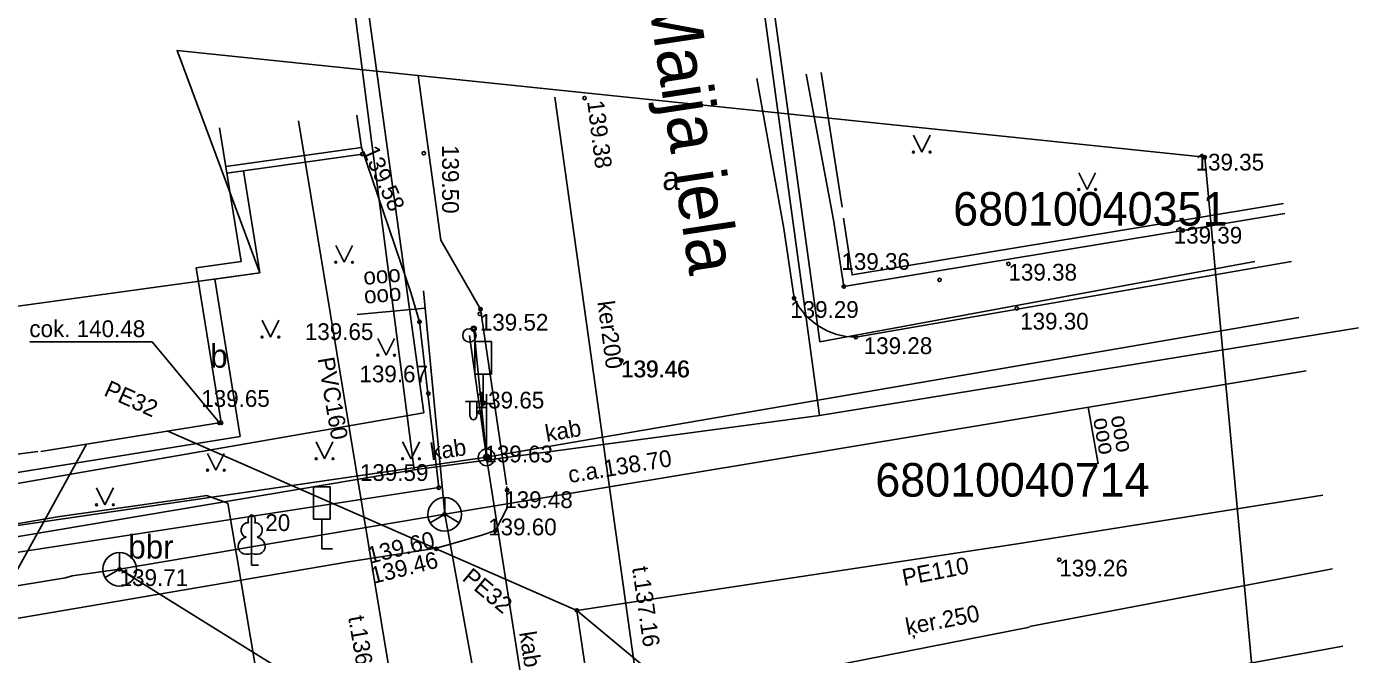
# Model space of a CAD drawing. Extents: x 728492 to 729038, y 272968 to 273171.
# Drawn here: x 728950.66 to 728990.4, y 273126.6 to 273145.31 of the extents above; entities that cross this region are included whole.
import ezdxf

# ---------------------------------------------------------------- set-up
doc = ezdxf.new("R2010")
doc.units = 0
for name, color, linetype in [('APGR_SARK_####_####_#', 7, 'Continuous'), ('APGS_ELEM_####_####_#', 7, 'Continuous'), ('BUVE_BDET_####_####_#', 7, 'Continuous'), ('BUVE_BDET_####_TKST_#', 7, 'Continuous'), ('BUVE_EKAS_####_####_#', 7, 'Continuous'), ('CELI_CAPM_####_####_#', 7, 'Continuous'), ('CELI_CMAL_####_####_#', 7, 'Continuous'), ('CELI_CSEG_####_TKST_#', 7, 'Continuous'), ('CELI_ELEM_####_####_#', 7, 'Continuous'), ('CELI_IELA_####_TKST_#', 7, 'Continuous'), ('ELEK_ELEM_####_####_#', 7, 'Continuous'), ('ELEK_SAIT_####_####_#', 7, 'Continuous'), ('ELEK_STUT_####_####_#', 7, 'Continuous'), ('ELEK_VADP_ZSPR_####_#', 7, 'Continuous'), ('ELEK_VADV_ZSPR_####_#', 7, 'Continuous'), ('ELEK_VADV_ZSPR_TKST_#', 7, 'Continuous'), ('RAMI_UZMR_####_####_#', 7, 'Continuous'), ('RELJ_AATZ_####_TKST_#', 7, 'Continuous'), ('RELJ_ELEM_####_####_#', 7, 'Continuous'), ('ROBZ_KADS_####_TKST_#', 7, 'Continuous'), ('ROBZ_UZMR_####_####_#', 7, 'Continuous'), ('SAKK_ELEM_####_####_#', 7, 'Continuous'), ('SAKK_ELEM_####_TKST_#', 7, 'Continuous'), ('SAKK_IZVK_####_TKST_#', 7, 'Continuous'), ('SAKK_KKAN_####_####_#', 7, 'Continuous'), ('SAKK_KKAN_####_TKST_#', 7, 'Continuous'), ('SKAN_VADP_PAST_####_#', 7, 'Continuous'), ('SKAN_VADP_PAST_TKST_#', 7, 'Continuous'), ('TERT_DIAM_####_TKST_#', 7, 'Continuous'), ('TERT_ELEM_####_####_#', 7, 'Continuous'), ('TERT_KRND_####_####_#', 7, 'Continuous'), ('UDTK_VADP_UDEN_####_#', 7, 'Continuous'), ('UDTK_VADP_UDEN_TKST_#', 7, 'Continuous')]:
    doc.layers.add(name, color=color, linetype=linetype)

msp = doc.modelspace()

# ---------------------------------------------------------------- linework, layer by layer
at = {"layer": 'APGR_SARK_####_####_#'}
for points in [[(728971.466, 273156.636), (728974.331, 273135.918)], [(728959.442, 273155.987), (728962.51, 273133.798)], [(728987.311, 273138.313), (728974.331, 273135.918)], [(728962.51, 273133.798), (728824.842, 273109.886)]]:
    msp.add_lwpolyline(points, dxfattribs=at)
at = {"layer": 'APGS_ELEM_####_####_#'}
for p, q in [((728964.384, 273134.141), (728963.749, 273134.136)), ((728963.884, 273134.137), (728963.884, 273133.745)), ((728964.094, 273134.139), (728964.094, 273133.745)), ((728964.384, 273132.474), (728964.384, 273134.357))]:
    msp.add_line(p, q, dxfattribs=at)
msp.add_circle((728964.384, 273132.474), 0.09, dxfattribs=at)
msp.add_ellipse((728963.989, 273133.745), major_axis=(0, 0.151), ratio=0.695971, start_param=1.570796, end_param=4.712389, dxfattribs=at)
at = {"layer": 'BUVE_BDET_####_####_#'}
for p, q in [((728960.512, 273142.669), (728960.647, 273141.71)), ((728956.632, 273140.942), (728960.675, 273141.512))]:
    msp.add_line(p, q, dxfattribs=at)
for points in [[(728956.6, 273141.139), (728960.647, 273141.71)], [(728956.408, 273133.502), (728954.399, 273135.921), (728950.756, 273135.921)]]:
    msp.add_lwpolyline(points, dxfattribs=at)
at = {"layer": 'BUVE_EKAS_####_####_#'}
for p, q in [((728956.414, 273142.292), (728957.056, 273138.312)), ((728957.056, 273138.312), (728955.717, 273138.126)), ((728955.717, 273138.126), (728956.461, 273133.51)), ((728956.461, 273133.51), (728951.086, 273132.644)), ((728950.987, 273132.646), (728940.375, 273131.284))]:
    msp.add_line(p, q, dxfattribs=at)
at = {"layer": 'CELI_CAPM_####_####_#'}
for p, q in [((728973.557, 273137.215), (728973.25, 273139.293)), ((728989.936, 273126.847), (728980.849, 273125.181))]:
    msp.add_line(p, q, dxfattribs=at)
for points in [[(728962.343, 273143.855), (728963.022, 273138.947)], [(728973.25, 273139.293), (728972.448, 273143.766)], [(728962.134, 273137.359), (728960.647, 273141.71)], [(728964.201, 273136.893), (728963.022, 273138.947)], [(728988.398, 273138.308), (728979.478, 273136.762)], [(728964.181, 273136.95), (728964.201, 273136.893), (728964.978, 273131.657)], [(728979.478, 273136.762), (728975.402, 273136.055)], [(728962.885, 273129.761), (728960.258, 273129.36), (728940.62, 273126.01)]]:
    msp.add_lwpolyline(points, dxfattribs=at)
msp.add_arc((728975.417, 273138.126), 2.071, 206.0978, 269.5849, dxfattribs=at)
at = {"layer": 'CELI_CMAL_####_####_#'}
for p, q in [((728957.127, 273141.012), (728957.616, 273137.975)), ((728957.616, 273137.975), (728956.278, 273137.789)), ((728956.278, 273137.789), (728957.034, 273133.096)), ((728957.034, 273133.096), (728947.609, 273131.578)), ((728948.069, 273129.288), (728962.958, 273131.569))]:
    msp.add_line(p, q, dxfattribs=at)
for points in [[(728973.921, 273143.901), (728974.734, 273139.549)], [(728979.3, 273138.27), (728985.157, 273139.238), (728988.205, 273139.745)], [(728974.734, 273139.549), (728975.04, 273137.566), (728979.3, 273138.27)], [(728962.958, 273131.569), (728962.958, 273131.569), (728962.381, 273136.517), (728962.134, 273137.359)], [(728962.885, 273129.761), (728964.244, 273130.148), (728964.646, 273130.296), (728964.996, 273130.969), (728964.983, 273131.606)]]:
    msp.add_lwpolyline(points, dxfattribs=at)
at = {"layer": 'CELI_ELEM_####_####_#'}
for p, q in [((728964.528, 273135.924), (728964.028, 273135.924)), ((728964.028, 273134.955), (728964.028, 273135.924)), ((728964.528, 273134.955), (728964.528, 273135.924)), ((728964.528, 273134.955), (728964.028, 273134.955)), ((728964.282, 273134.955), (728964.282, 273134.077)), ((728964.282, 273134.077), (728964.597, 273134.077)), ((728959.715, 273131.597), (728959.215, 273131.597)), ((728959.215, 273130.628), (728959.215, 273131.597)), ((728959.715, 273130.628), (728959.715, 273131.597)), ((728959.715, 273130.628), (728959.215, 273130.628)), ((728959.469, 273130.628), (728959.469, 273129.75)), ((728959.469, 273129.75), (728959.784, 273129.75))]:
    msp.add_line(p, q, dxfattribs=at)
at = {"layer": 'ELEK_ELEM_####_####_#'}
for centre, radius in [((728963.87, 273136.108), 0.2), ((728964.384, 273132.474), 0.25)]:
    msp.add_circle(centre, radius, dxfattribs=at)
at = {"layer": 'ELEK_SAIT_####_####_#'}
msp.add_line((728964, 273136.308), (728964.384, 273132.474), dxfattribs=at)
msp.add_circle((728964, 273136.308), 0.075, dxfattribs=at)
at = {"layer": 'ELEK_STUT_####_####_#'}
msp.add_line((728964.384, 273132.474), (728963.87, 273136.108), dxfattribs=at)
at = {"layer": 'ELEK_VADP_ZSPR_####_#'}
for points in [[(728951.576, 273130.701), (728955.714, 273131.287), (728956.029, 273131.332), (728956.659, 273131.106), (728958.413, 273120.742), (728958.908, 273120.382), (728961.741, 273120.562), (728963.406, 273120.427), (728964.62, 273119.841), (728965.655, 273118.625), (728967.754, 273104.979)], [(728951.576, 273130.701), (728946.768, 273129.874), (728931.098, 273127.179), (728928.944, 273126.808), (728928.895, 273127.096)]]:
    msp.add_lwpolyline(points, dxfattribs=at)
at = {"layer": 'ELEK_VADV_ZSPR_####_#'}
for p, q in [((728964.384, 273132.474), (728988.622, 273136.638)), ((728936.036, 273128.36), (728964.384, 273132.474)), ((728964.384, 273132.474), (728968.655, 273105.196))]:
    msp.add_line(p, q, dxfattribs=at)
at = {"layer": 'RAMI_UZMR_####_####_#'}
msp.add_lwpolyline([(728688.721, 273058.407), (728702.149, 273066.922), (728733.452, 273072.937), (728813.127, 273088.247), (728815.181, 273072.879), (728831.342, 273076.994), (728831.817, 273091.35), (728930.137, 273106.573), (728962.389, 273111.567), (728966.363, 273103.835), (728988.796, 273109.153), (728985.811, 273141.417), (728955.146, 273144.603), (728957.616, 273137.975), (728904.333, 273130.641), (728847.677, 273120.095), (728823.483, 273119.793), (728790.036, 273112.558), (728726.814, 273102.175), (728686.914, 273096.216)], dxfattribs=at)
at = {"layer": 'RELJ_ELEM_####_####_#'}
for centre, radius in [((728967.306, 273143.185), 0.05), ((728960.675, 273141.512), 0.05), ((728962.51, 273141.538), 0.05), ((728985.811, 273141.417), 0.05), ((728985.157, 273139.238), 0.05), ((728979.956, 273138.241), 0.05), ((728977.899, 273137.761), 0.05), ((728975.04, 273137.566), 0.05), ((728964.201, 273136.893), 0.05), ((728973.557, 273137.215), 0.05), ((728980.202, 273136.912), 0.05), ((728962.381, 273136.517), 0.05), ((728964.181, 273136.75), 0.05), ((728964, 273136.308), 0.05), ((728975.402, 273136.055), 0.05), ((728968.407, 273135.359), 0.05), ((728962.648, 273134.375), 0.05), ((728964.282, 273134.077), 0.05), ((728964.181, 273133.816), 0.05), ((728956.408, 273133.502), 0.0534), ((728956.461, 273133.502), 0.05), ((728964.384, 273132.474), 0.0534), ((728962.958, 273131.569), 0.05), ((728964.995, 273131.495), 0.05), ((728963.132, 273130.774), 0.05), ((728964.646, 273130.296), 0.05), ((728962.876, 273129.745), 0.05), ((728981.473, 273129.421), 0.05), ((728953.432, 273129.137), 0.05), ((728967.08, 273127.91), 0.05)]:
    msp.add_circle(centre, radius, dxfattribs=at)
at = {"layer": 'ROBZ_UZMR_####_####_#'}
for p, q in [((728972.359, 273148.016), (728974.322, 273133.72)), ((728962.218, 273132.099), (728960.199, 273147.729)), ((728974.322, 273133.72), (728990.397, 273136.336)), ((728974.322, 273133.72), (728962.218, 273132.099)), ((728962.218, 273132.099), (728918.09, 273124.69))]:
    msp.add_line(p, q, dxfattribs=at)
at = {"layer": 'SAKK_ELEM_####_####_#'}
for p, q in [((728963.132, 273130.774), (728963.132, 273131.273)), ((728962.698, 273130.524), (728963.132, 273130.774)), ((728963.132, 273130.774), (728963.131, 273130.773)), ((728963.565, 273130.524), (728963.132, 273130.774)), ((728953.432, 273129.137), (728953.432, 273129.636)), ((728952.998, 273128.887), (728953.432, 273129.137)), ((728953.432, 273129.137), (728953.431, 273129.136)), ((728953.865, 273128.887), (728953.432, 273129.137))]:
    msp.add_line(p, q, dxfattribs=at)
for centre in [(728963.132, 273130.772), (728953.432, 273129.135)]:
    msp.add_circle(centre, 0.5, dxfattribs=at)
at = {"layer": 'SAKK_IZVK_####_TKST_#'}
for p, q in [((728960.524, 273136.727), (728962.553, 273136.919)), ((728982.33, 273133.965), (728982.628, 273132.28))]:
    msp.add_line(p, q, dxfattribs=at)
at = {"layer": 'SAKK_KKAN_####_####_#'}
for points in [[(728963.132, 273130.774), (728962.504, 273137.438)], [(728979.858, 273133.555), (728988.836, 273135.047)], [(728963.132, 273130.774), (728979.858, 273133.555)], [(728963.132, 273130.774), (728953.432, 273129.137), (728952.016, 273128.94)], [(728963.132, 273130.774), (728964.707, 273122.13)], [(728951.822, 273128.885), (728952.016, 273128.94)], [(728953.432, 273129.137), (728964.707, 273122.13)], [(728822.033, 273123.296), (728824.535, 273107.953), (728848.919, 273112.053), (728887.446, 273118.532), (728897.906, 273120.141), (728908.778, 273121.814), (728951.822, 273128.885)]]:
    msp.add_lwpolyline(points, dxfattribs=at)
at = {"layer": 'SKAN_VADP_PAST_####_#'}
for points in [[(728968.957, 273125.121), (728966.415, 273143.211)], [(728958.775, 273142.509), (728961.809, 273124.096)], [(728946.06, 273121.302), (728952.446, 273132.863)], [(728989.628, 273129.146), (728980.584, 273127.426)], [(728980.586, 273127.408), (728968.957, 273125.121)]]:
    msp.add_lwpolyline(points, dxfattribs=at)
at = {"layer": 'TERT_ELEM_####_####_#'}
for p, q in [((728977.118, 273142.073), (728977.368, 273141.573)), ((728977.368, 273141.573), (728977.618, 273142.073)), ((728982.056, 273140.959), (728982.306, 273140.459)), ((728982.306, 273140.459), (728982.556, 273140.959)), ((728959.88, 273138.788), (728960.13, 273138.288)), ((728960.13, 273138.288), (728960.38, 273138.788)), ((728957.682, 273136.56), (728957.932, 273136.06)), ((728957.932, 273136.06), (728958.182, 273136.56)), ((728961.136, 273136.017), (728961.386, 273135.517)), ((728961.386, 273135.517), (728961.636, 273136.017)), ((728959.299, 273132.932), (728959.549, 273132.432)), ((728959.549, 273132.432), (728959.799, 273132.932)), ((728961.878, 273132.932), (728962.128, 273132.432)), ((728962.128, 273132.432), (728962.378, 273132.932)), ((728956.056, 273132.588), (728956.306, 273132.088)), ((728956.306, 273132.088), (728956.556, 273132.588)), ((728952.745, 273131.56), (728952.995, 273131.06)), ((728952.995, 273131.06), (728953.245, 273131.56)), ((728957.372, 273129.602), (728957.372, 273129.255)), ((728957.372, 273129.255), (728957.572, 273129.255))]:
    msp.add_line(p, q, dxfattribs=at)
for points in [[(728957.372, 273130.755), (728957.372, 273129.602)], [(728957.461, 273130.522), (728957.46, 273130.523)]]:
    msp.add_lwpolyline(points, dxfattribs=at)
for centre, radius in [((728977.118, 273141.573), 0.028), ((728977.618, 273141.573), 0.0263), ((728982.055, 273140.459), 0.028), ((728982.555, 273140.459), 0.0263), ((728959.88, 273138.287), 0.028), ((728960.38, 273138.287), 0.0263), ((728957.682, 273136.059), 0.028), ((728958.182, 273136.059), 0.0263), ((728961.136, 273135.516), 0.028), ((728961.636, 273135.516), 0.0263), ((728956.055, 273132.088), 0.028), ((728956.555, 273132.088), 0.0263), ((728959.299, 273132.432), 0.028), ((728959.799, 273132.432), 0.0263), ((728961.878, 273132.432), 0.028), ((728962.378, 273132.432), 0.0263), ((728952.745, 273131.059), 0.028), ((728953.245, 273131.059), 0.0263)]:
    msp.add_circle(centre, radius, dxfattribs=at)
for centre, major_axis, ratio, start_param, end_param in [((728957.244, 273130.31), (-0.039, -0.212), 0.861323, 3.141593, 6.283185), ((728957.372, 273130.605), (0, -0.15), 0.707107, 3.14537, 5.287485), ((728957.372, 273130.605), (0, -0.15), 0.707107, 0.995701, 3.137816), ((728957.5, 273130.31), (0.039, -0.212), 0.861323, 0, 3.141593), ((728957.282, 273129.848), (0.307, 0.095), 0.814445, 1.570796, 4.752015), ((728957.461, 273129.848), (-0.307, 0.095), 0.814445, 1.531171, 4.712389)]:
    msp.add_ellipse(centre, major_axis=major_axis, ratio=ratio, start_param=start_param, end_param=end_param, dxfattribs=at)
at = {"layer": 'TERT_KRND_####_####_#'}
for points in [[(728974.994, 273139.931), (728974.369, 273143.942)], [(728988.165, 273140.043), (728985.108, 273139.534), (728979.264, 273138.568)], [(728979.264, 273138.568), (728975.29, 273137.911), (728975.03, 273139.6)]]:
    msp.add_lwpolyline(points, dxfattribs=at)
at = {"layer": 'UDTK_VADP_UDEN_####_#'}
msp.add_line((728967.08, 273127.91), (728967.741, 273123.352), dxfattribs=at)
for points in [[(728967.08, 273127.91), (728954.874, 273133.254)], [(728989.333, 273131.342), (728980.29, 273129.903)], [(728980.29, 273129.903), (728967.08, 273127.91)], [(728967.08, 273127.91), (728973.084, 273122.906), (728973.569, 273119.035)]]:
    msp.add_lwpolyline(points, dxfattribs=at)

# ---------------------------------------------------------------- texts
at = {"layer": 'BUVE_BDET_####_TKST_#'}
msp.add_text('cok. 140.48', height=0.5, dxfattribs=at).set_placement((728950.739, 273136.057))
at = {"layer": 'CELI_CSEG_####_TKST_#'}
for s, p in [('a', (728969.625, 273140.443)), ('b', (728956.136, 273135.145)), ('bbr', (728953.691, 273129.456))]:
    msp.add_text(s, height=0.7, dxfattribs=at).set_placement(p)
at = {"layer": 'CELI_IELA_####_TKST_#'}
msp.add_text('1.Maija iela', height=1.5, rotation=278.5972, dxfattribs=at).set_placement((728968.927, 273147.9))
at = {"layer": 'ELEK_VADV_ZSPR_TKST_#'}
for rotation, p in [(9.7491, (728966.176, 273132.934)), (8.2583, (728962.736, 273132.386)), (278.8998, (728965.354, 273127.247))]:
    msp.add_text('kab', height=0.5, rotation=rotation, dxfattribs=at).set_placement(p)
at = {"layer": 'RELJ_AATZ_####_TKST_#'}
for s, rotation, p in [('139.38', 277.04, (728967.383, 273143.087)), ('139.58', 294.2101, (728960.667, 273141.621)), ('139.50', 270, (728963.057, 273141.784)), ('139.60', 14.1836, (728960.894, 273129.294)), ('139.46', 14.0474, (728960.993, 273128.696))]:
    msp.add_text(s, height=0.5, rotation=rotation, dxfattribs=at).set_placement(p)
for s, p in [(' 139.35', (728985.355, 273141.024)), (' 139.39', (728984.701, 273138.845)), (' 139.36', (728974.785, 273138.061)), ('139.38', (728979.956, 273137.741)), ('139.29', (728973.443, 273136.63)), ('139.52', (728964.181, 273136.25)), ('139.30', (728980.305, 273136.281)), (' 139.65', (728958.774, 273135.971)), (' 139.28', (728975.451, 273135.552)), ('139.46', (728968.39, 273134.857)), ('139.46', (728968.407, 273134.859)), ('139.67', (728960.589, 273134.71)), (' 139.65', (728955.683, 273133.977)), (' 139.65', (728963.873, 273133.929)), (' 139.63', (728964.132, 273132.323)), ('139.59', (728960.602, 273131.769)), ('139.48', (728964.91, 273130.96)), ('139.26', (728981.473, 273128.921))]:
    msp.add_text(s, height=0.5, dxfattribs=at).set_placement(p)
at = {"layer": 'ROBZ_KADS_####_TKST_#'}
for s, p in [('68010040351', (728978.308, 273139.38)), ('68010040714', (728975.984, 273131.302))]:
    msp.add_text(s, height=1, dxfattribs=at).set_placement(p)
at = {"layer": 'SAKK_ELEM_####_TKST_#'}
for s, p in [(' 139.60', (728964.244, 273130.148)), ('139.71', (728953.432, 273128.637))]:
    msp.add_text(s, height=0.5, dxfattribs=at).set_placement(p)
at = {"layer": 'SAKK_KKAN_####_TKST_#'}
for s, rotation, p in [('ooo', 5.3819, (728960.727, 273137.611)), ('ooo', 5.3819, (728960.746, 273137.05)), ('ooo', 280.0541, (728983.005, 273133.687)), ('ooo', 280.0541, (728982.481, 273133.62)), ('c.a.138.70', 9.4386, (728966.858, 273131.703))]:
    msp.add_text(s, height=0.5, rotation=rotation, dxfattribs=at).set_placement(p)
at = {"layer": 'SKAN_VADP_PAST_TKST_#'}
for s, rotation, p in [('ker200', 277.4576, (728967.69, 273137.108)), ('PVC160', 279.7272, (728959.339, 273135.419)), ('t.137.16', 278.1242, (728968.724, 273129.185)), ('t.136.98', 279.7272, (728960.25, 273127.71)), ('ķer.250', 10.8573, (728976.936, 273127.172))]:
    msp.add_text(s, height=0.5, rotation=rotation, dxfattribs=at).set_placement(p)
at = {"layer": 'TERT_DIAM_####_TKST_#'}
msp.add_text('20', height=0.5, dxfattribs=at).set_placement((728957.779, 273130.276))
at = {"layer": 'UDTK_VADP_UDEN_TKST_#'}
for s, rotation, p in [('PE32', 335.6663, (728952.932, 273134.33)), ('PE110', 11.0497, (728976.837, 273128.637)), ('PE32', 320.1907, (728963.625, 273128.829))]:
    msp.add_text(s, height=0.5, rotation=rotation, dxfattribs=at).set_placement(p)

doc.saveas('drawing.dxf')
